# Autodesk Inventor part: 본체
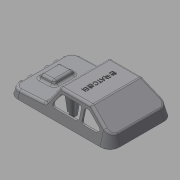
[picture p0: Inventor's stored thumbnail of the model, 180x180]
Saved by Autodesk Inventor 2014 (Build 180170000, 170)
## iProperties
Created: 2007-09
Part Number: 본체
Material: Generic
Document SubType Name: Modeling
Designer: Administrator
Density: 1 g/cm^3
Appearance: Default
Author: Administrator
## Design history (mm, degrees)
sketch "스케치1"
  geometry: L1 (49, 38)-(-49, 38); L2 (-61, 26)-(-61, -26); L3 (-49, -38)-(49, -38); L4 (61, -26)-(61, 26); L5 (61, 38)-(-61, -38); L6 (-61, 38)-(61, -38); A1 r 12 centre (-49, 26) between (-49, 38) and (-61, 26); A2 r 12 centre (49, 26) between (61, 26) and (49, 38); A3 r 12 centre (49, -26) between (49, -38) and (61, -26); A4 r 12 centre (-49, -26) between (-61, -26) and (-49, -38); 1 further point
  constraints: 12 end point, 8 point on circle, 8 point on line, 8 tangent, 4 centre point, 3 equal radius, 2 midpoint, 2 parallel, 1 horizontal, 1 perpendicular
  dimensions: "d0" = 122 distance of L6.end L5.end; "d1" = 76 distance of L5.end L6.start; "d2" = 12 radius of A1
extrude "돌출1" new body sketch "스케치1" distance "d3" = 30; taper "d4" = -15 deg
sketch "스케치2"
  geometry: L1 (49, 30)-(-49, 30) reference; L2 (-49, 0)-(-61, 0) reference; L3 (-31, 30)-(-61, 30); L4 (-61, 30)-(-61, 10); L5 (-61, 10)-(-31, 30); 1 further point
  constraints: 6 end point, 1 collinear, 1 parallel, 1 perpendicular, 1 vertical alignment
  dimensions: "d6" = 20 distance of L3.end L4.end; "d7" = 30 distance of L3.start L3.end
extrude "돌출2" cut sketch "스케치2" stored distance "d8" = 10; taper "d9" = 0 deg
sketch "스케치3"
  geometry: L1 (61, 30)-(6.628, 30); L2 (6.628, 30)-(19, 10.201); L3 (19, 10.201)-(61, 8); L4 (61, 8)-(61, 30); L5 (49, 30)-(-31, 30) reference; L6 (61, 0)-(49, 0) reference; L7 (-49, 0)-(49, 0) reference; 1 further point
  constraints: 8 end point, 1 collinear, 1 horizontal, 1 perpendicular, 1 vertical alignment
  dimensions: "d10" = 8 distance of L6.start L3.end; "d11" = 3 deg angle of L7 L3; "d12" = 125 deg angle of L3 L2; "d13" = 42 horizontal distance of L2.end L6.start
extrude "돌출3" cut sketch "스케치3" stored distance "d14" = 10; taper "d15" = 0 deg
sketch "스케치4"
  geometry: L1 (-39.881, 9.267)-(-39.881, 61.267) reference; L2 (-31.476, 48.267)-(-11.476, 48.267); L3 (-11.476, 48.267)-(-11.476, 22.267); L4 (-11.476, 22.267)-(-31.476, 22.267); L5 (-31.476, 22.267)-(-31.476, 48.267); L6 (-42.476, 61.267)-(-42.476, 9.267) reference; 3 further points
  constraints: 8 end point, 2 midpoint, 2 parallel, 1 horizontal, 1 horizontal alignment, 1 perpendicular
  dimensions: "d16" = 20 distance between parallel lines of L5 L3; "d17" = 26 distance between parallel lines of L4 L2; "d82" = 11 distance between parallel lines of L5 L6
extrude "돌출4" join sketch "스케치4" distance "d19" = 5; taper "d20" = -20 deg
fillet "모깎기1" dims "d21" = 3
fillet "모깎기2" dims "d22" = 3
fillet "모깎기3" dims "d23" = 3
fillet "모깎기4" dims "d24" = 3
fillet "모깎기5" dims "d25" = 3
feature "쉘1" dims "d26" = 2
sketch "스케치7"
  geometry: L1 (18.172, 11.526)-(7.51, 28.59) reference; L2 (4.965, 30)-(-30.092, 30) reference; L3 (-31.756, 29.496)-(-50.664, 16.891) reference; L4 (10.362, 14.59)-(4.738, 23.59); L5 (2.194, 25)-(-17.77, 25); L6 (7.818, 10)-(-17.77, 10); L7 (-20.77, 13)-(-20.77, 22); L8 (-30.242, 24.496)-(-43.742, 15.496); L9 (-42.078, 10)-(-26.986, 10); L10 (-23.986, 13)-(-23.986, 22); L11 (-26.986, 25)-(-28.578, 25); A1 r 3 centre (-17.77, 13) between (-20.77, 13) and (-17.77, 10); A2 r 3 centre (-17.77, 22) between (-17.77, 25) and (-20.77, 22); A3 r 3 centre (2.194, 22) between (4.738, 23.59) and (2.194, 25); A4 r 3 centre (7.818, 13) between (7.818, 10) and (10.362, 14.59); A5 r 3 centre (-42.078, 13) between (-43.742, 15.496) and (-42.078, 10); A6 r 3 centre (-26.986, 13) between (-26.986, 10) and (-23.986, 13); A7 r 3 centre (-26.986, 22) between (-23.986, 22) and (-26.986, 25); A8 r 3 centre (-28.578, 22) between (-28.578, 25) and (-30.242, 24.496); 7 further points
  constraints: 16 end point, 16 point on circle, 16 tangent, 12 point on line, 8 centre point, 6 equal radius, 5 parallel, 3 perpendicular
  dimensions: "d27" = 5 distance between parallel lines of L2 L5; "d28" = 5 distance between parallel lines of L1 L4; "d29" = 34 distance of point (13.23, 10) point (-20.77, 10); "d30" = 15 distance of point (-20.77, 10) point (-20.77, 25); "d31" = 3 radius of A1; "d32" = 5 distance between parallel lines of L3 L8; "d33" = 5 distance between parallel lines of L2 L11; "d34" = 28 distance of point (-51.986, 10) point (-23.986, 10); "d35" = 15 distance of point (-23.986, 10) point (-23.986, 25); "d36" = 3 radius of A5
extrude "돌출5" cut sketch "스케치7" stored distance "d37" = 5; taper "d38" = 0 deg
sketch "스케치8"
  geometry: L1 (-49, 35.929)-(49, 35.929) reference; L2 (58.929, 26)-(58.929, -26) reference; L3 (49, -35.929)-(-49, -35.929) reference; L4 (-58.929, -26)-(-58.929, 26) reference; L5 (49, 36.929)-(-49, 36.929); L6 (-59.929, 26)-(-59.929, -26); L7 (-49, -36.929)-(49, -36.929); L8 (59.929, -26)-(59.929, 26); A1 r 9.929 centre (49, 26) between (58.929, 26) and (49, 35.929) reference; A2 r 9.929 centre (49, -26) between (49, -35.929) and (58.929, -26) reference; A3 r 9.929 centre (-49, -26) between (-58.929, -26) and (-49, -35.929) reference; A4 r 9.929 centre (-49, 26) between (-49, 35.929) and (-58.929, 26) reference; A5 r 10.929 centre (-49, 26) between (-49, 36.929) and (-59.929, 26); A6 r 10.929 centre (-49, -26) between (-59.929, -26) and (-49, -36.929); A7 r 10.929 centre (49, -26) between (49, -36.929) and (59.929, -26); A8 r 10.929 centre (49, 26) between (59.929, 26) and (49, 36.929); 1 further point
  constraints: 8 end point, 8 point on circle, 4 centre point, 7 other
  dimensions: "d39" = 1 distance between parallel lines of L5 L1
extrude "돌출6" join sketch "스케치8" distance "d40" = 1; taper "d41" = 0 deg
node "작업 평면1"
sketch "스케치9"
  geometry: A1 r 4 centre (21, 0) between (25, 0) and (17, 0); A2 r 4 centre (10, 0) between (14, 0) and (6, 0); A3 r 4 centre (-10, 0) between (-6, 0) and (-14, 0); A4 r 4 centre (-21, 0) between (-17, 0) and (-25, 0); 3 further points
  constraints: 8 point on circle, 4 centre point, 13 other
  dimensions: "d43" = 8 diameter of A1; "d44" = 8 diameter of A2; "d45" = 8 diameter of A3; "d46" = 8 diameter of A4; "d47" = 20 distance of A3.centre A2.centre; "d48" = 10 distance of point (0, 0) A2.centre; "d49" = 11 distance of A1.centre A2.centre; "d50" = 11 distance of A4.centre A3.centre
extrude "돌출7" join sketch "스케치9" stored distance "d51" = 1; taper "d52" = 0 deg
sketch "스케치13"
  geometry: C1 r 3 at (-40, 0); C2 r 3 at (40, 0); C3 r 3 at (0, -22); C4 r 3 at (0, 22); 1 further point
  constraints: 4 centre point, 2 horizontal alignment, 2 vertical alignment
  dimensions: "d83" = 6 diameter of C1; "d84" = 6 diameter of C2; "d85" = 6 diameter of C3; "d86" = 6 diameter of C4; "d87" = 44 distance of C3.centre C4.centre; "d88" = 22 distance of C3.centre point (0, 0); "d89" = 40 distance of C1.centre point (0, 0); "d90" = 40 distance of C2.centre point (0, 0)
extrude "돌출10" join sketch "스케치13" stored distance "d91" = 1; taper "d92" = 2 deg
node "작업 평면3"
sketch "스케치14"
  geometry: L1 (-45, 1)-(-35, 1); L2 (-35, 1)-(-35, -1); L3 (-35, -1)-(-45, -1); L4 (-45, -1)-(-45, 1); L5 (-45, 1)-(-35, -1); L6 (-35, 1)-(-45, -1); L7 (5, 23)-(-5, 23); L8 (-5, 23)-(-5, 21); L9 (-5, 21)-(5, 21); L10 (5, 21)-(5, 23); L11 (5, 23)-(-5, 21); L12 (-5, 23)-(5, 21); L13 (35, 1)-(45, 1); L14 (45, 1)-(45, -1); L15 (45, -1)-(35, -1); L16 (35, -1)-(35, 1); L17 (35, 1)-(45, -1); L18 (45, 1)-(35, -1); L19 (5, -21)-(-5, -21); L20 (-5, -21)-(-5, -23); L21 (-5, -23)-(5, -23); L22 (5, -23)-(5, -21); L23 (5, -21)-(-5, -23); L24 (-5, -21)-(5, -23); C1 r 3 at (0, -22) reference; C2 r 3 at (0, 22) reference; C3 r 3 at (40, 0) reference; C4 r 3 at (-40, 0) reference; 1 further point
  constraints: 48 end point, 8 midpoint, 8 parallel, 4 horizontal, 4 perpendicular
  dimensions: "d94" = 10 distance of L2.end L3.end; "d95" = 2 distance of L1.end L2.end; "d96" = 10 distance of L9.end L8.end; "d97" = 2 distance of L8.end L7.end; "d98" = 10 distance of L14.end L15.end; "d99" = 2 distance of L13.end L14.end; "d100" = 10 distance of L21.end L20.end; "d101" = 2 distance of L20.end L19.end
extrude "돌출11" join sketch "스케치14" stored distance "d102" = 1; taper "d103" = 0.5 deg
sketch "스케치15"
  geometry: L1 (2.098, 0)-(2.324, -26.001) reference; L2 (2.098, 0)-(6.682, -26.001); L3 (27.189, -27.941)-(-7.868, -27.941) reference; L4 (2.324, -26.001)-(6.682, -26.001); 1 further point
  constraints: 4 end point, 1 parallel
  dimensions: "d104" = 80 deg angle of L3 L2
extrude "돌출12" join sketch "스케치15" stored distance "d105" = 1; taper "d106" = 0 deg
sketch "스케치16"
  geometry: L1 (0, 0)-(-3.68, -20.872); L2 (35.092, -27.941)-(0.035, -27.941) reference; L3 (-0.813, -25.471)-(-11.476, -8.367) reference; L4 (-3.68, -20.872)-(0.035, -27.941); L5 (0.035, -27.941)-(0, 0); 1 further point
  constraints: 6 end point, 1 point on line
  dimensions: "d107" = 100 deg angle of L2 L1
extrude "돌출13" join sketch "스케치16" stored distance "d108" = 1; taper "d109" = 0 deg
sketch "스케치17"
  geometry: L1 (0, 0)-(-0.201, -23.065) reference; L2 (0, 0)-(-4.89, -27.73); L3 (-4.908, -27.749)-(-39.965, -27.749) reference; L4 (-4.908, -27.749)-(-0.201, -23.065); L5 (0, 0)-(-0.201, -23.065); 1 further point
  constraints: 6 end point, 1 collinear, 1 point on line
  dimensions: "d110" = 100 deg angle of L3 L2
extrude "돌출14" join sketch "스케치17" stored distance "d111" = 1; taper "d112" = 0 deg
sketch "스케치18"
  geometry: L1 (-12.811, -27.749)-(-47.868, -27.749) reference; L2 (2.098, 0)-(4.62, -14.304); L3 (6.652, -12.946)-(-12.256, -25.581) reference; L4 (2.098, 0)-(2.239, -16.17); L5 (2.239, -16.17)-(4.62, -14.304); 1 further point
  constraints: 6 end point, 1 point on line
  dimensions: "d113" = 100 deg angle of L2 L1
extrude "돌출15" join sketch "스케치18" stored distance "d114" = 1; taper "d115" = 0 deg
sketch "스케치19"
  geometry: L1 (1.761, -9.935)-(-0.086, -9.839) reference; L2 (0, 0)-(-0.086, -9.839) reference; L3 (0, 0)-(-1.72, -9.753); L4 (75.092, -27.749)-(40.035, -27.749) reference; L5 (10.467, -10.303)-(-1.675, -9.667) reference; L6 (0, 0)-(-0.086, -9.839); L7 (10.363, -12.3)-(-1.78, -11.664) reference; L8 (-1.676, -9.668)-(10.466, -10.304) reference; L9 (-1.72, -9.753)-(-0.086, -9.839); 3 further points; 2 other entities
  constraints: 6 end point, 1 point on line, 2 other
  dimensions: "d116" = 100 deg angle of L4 L3
extrude "돌출16" join sketch "스케치19" stored distance "d117" = 1; taper "d118" = 0 deg
sketch "스케치20"
  geometry: L1 (2.098, 0)-(2.188, -10.372) reference; L2 (2.098, 0)-(3.728, -9.246); L3 (67.189, -27.749)-(32.132, -27.749) reference; L4 (2.46, -12.3)-(-9.682, -11.664) reference; L5 (-9.579, -9.668)-(2.564, -10.304) reference; L6 (3.975, -8.661)-(3.538, -9.695) reference; L7 (2.098, 0)-(2.188, -10.372); L8 (3.943, -10.464)-(2.188, -10.372); L9 (3.728, -9.246)-(3.943, -10.464); 5 further points; 3 other entities
  constraints: 8 end point, 2 collinear, 1 point on line, 4 other
  dimensions: "d119" = 100 deg angle of L3 L2
extrude "돌출17" join sketch "스케치20" stored distance "d120" = 1; taper "d121" = 0 deg
sketch "스케치21"
  geometry: C1 r 3 at (0, 0) reference; C2 r 3 at (-40, -22) reference; C3 r 3 at (0, -44) reference; C4 r 3 at (40, -22) reference; 5 further points
  constraints: 4 coincident
hole "구멍1" sketch "스케치21" at (0, 0), (-40, -22), (0, -44), (40, -22) diameter "d122" = 3.242; stored, may be unused: countersink angle "d126" = 90 deg, drill point angle "d128" = 118 deg; dims "d123" = 9, "d124" = 4, "d125" = 2, "d127" = 11
sketch "스케치22"
  geometry: L1 (61, -26)-(61, 26) reference; 2 further points
  constraints: 1 horizontal alignment, 1 other
  dimensions: "d129" = 50 distance from line of point (11, 0) L1
feature "엠보싱1" sketch "스케치22" dims "d0" = 122, "d1" = 76, "d2" = 12, "d130" = 0.5, "d131" = 0
node "솔리드1"
mirror "대칭1"
node "투영된 루프4"
node "투영된 루프5"
node "투영된 루프6"
node "투영된 루프7"
node "투영된 루프8"
node "투영된 루프9"
node "투영된 루프10"
node "투영된 루프11"
node "투영된 루프12"
other parameters: "d42" = -63, "d93" = 2
